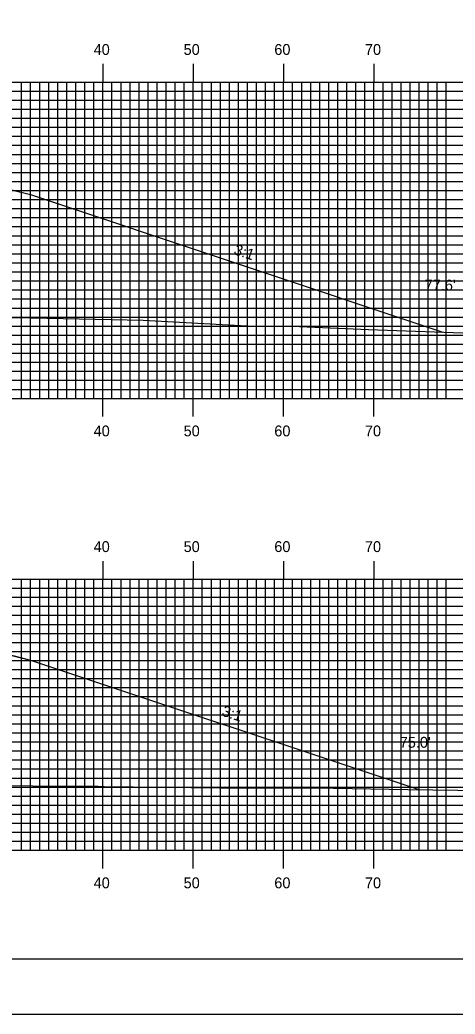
# Model space of a CAD drawing. Extents: x 1815702 to 1816046, y 442591 to 442811.
# Drawn here: x 1815898.9 to 1815947, y 442590.5 to 442700.5 of the extents above; entities that cross this region are included whole.
import ezdxf

# ---------------------------------------------------------------- set-up
doc = ezdxf.new("R2010")
doc.units = 0
for name, color, linetype in [('ANNOTATION', 7, 'Continuous'), ('BORDER', 7, 'Continuous'), ('D_Roadway_Centerline', 7, 'Continuous'), ('D_Roadway_SlopeLines', 7, 'Continuous'), ('D_Text_Standard', 7, 'Continuous'), ('H_V ANNOTATION', 7, 'Continuous'), ('MAJOR', 7, 'Continuous'), ('MINOR', 7, 'Continuous'), ('PLOT BOUNDARY', 7, 'Continuous'), ('S_Roadway_Centerline', 7, 'Continuous')]:
    doc.layers.add(name, color=color, linetype=linetype)

msp = doc.modelspace()

# ---------------------------------------------------------------- linework, layer by layer
at = {"layer": 'BORDER'}
msp.add_lwpolyline([(1815718.45, 442596.67), (1816038.45, 442596.67), (1816038.45, 442806.67), (1815718.45, 442806.67)], close=True, dxfattribs=at)
at = {"layer": 'D_Roadway_Centerline'}
for points in [[(1815809.89, 442672.49), (1815836.05, 442681.21), (1815837.87, 442681.67), (1815848.05, 442684.21), (1815856.05, 442684.53), (1815868.05, 442684.77), (1815880.05, 442684.53), (1815888.05, 442684.21), (1815898.22, 442681.67), (1815900.05, 442681.21), (1815945.68, 442666)], [(1815805.36, 442619.48), (1815836.05, 442629.71), (1815837.87, 442630.17), (1815848.05, 442632.71), (1815856.05, 442633.03), (1815868.05, 442633.27), (1815880.05, 442633.03), (1815888.05, 442632.71), (1815898.22, 442630.17), (1815900.05, 442629.71), (1815943, 442615.39)]]:
    msp.add_lwpolyline(points, dxfattribs=at)
at = {"layer": 'D_Roadway_SlopeLines'}
for points in [[(1815888.05, 442684.21), (1815900.05, 442681.21), (1815945.68, 442666)], [(1815888.05, 442632.71), (1815900.05, 442629.71), (1815943, 442615.39)]]:
    msp.add_lwpolyline(points, dxfattribs=at)
at = {"layer": 'MAJOR'}
for p, q in [((1815908.05, 442695.67), (1815908.05, 442693.67)), ((1815918.05, 442695.67), (1815918.05, 442693.67)), ((1815928.05, 442695.67), (1815928.05, 442693.67)), ((1815938.05, 442695.67), (1815938.05, 442693.67)), ((1815728.05, 442693.67), (1816008.05, 442693.67)), ((1815728.05, 442693.67), (1816008.05, 442693.67)), ((1815908.05, 442658.67), (1815908.05, 442693.67)), ((1815918.05, 442658.67), (1815918.05, 442693.67)), ((1815928.05, 442658.67), (1815928.05, 442693.67)), ((1815938.05, 442658.67), (1815938.05, 442693.67)), ((1815728.05, 442688.67), (1816008.05, 442688.67)), ((1815728.05, 442683.67), (1816008.05, 442683.67)), ((1815728.05, 442678.67), (1816008.05, 442678.67)), ((1815728.05, 442673.67), (1816008.05, 442673.67)), ((1815728.05, 442668.67), (1816008.05, 442668.67)), ((1815728.05, 442663.67), (1816008.05, 442663.67)), ((1815728.05, 442658.67), (1816008.05, 442658.67)), ((1815728.05, 442658.67), (1816008.05, 442658.67)), ((1815908.05, 442656.66), (1815908.05, 442658.67)), ((1815918.05, 442656.66), (1815918.05, 442658.67)), ((1815928.05, 442656.66), (1815928.05, 442658.67)), ((1815938.05, 442656.66), (1815938.05, 442658.67)), ((1815908.05, 442640.67), (1815908.05, 442638.67)), ((1815918.05, 442640.67), (1815918.05, 442638.67)), ((1815928.05, 442640.67), (1815928.05, 442638.67)), ((1815938.05, 442640.67), (1815938.05, 442638.67)), ((1815728.05, 442638.67), (1816008.05, 442638.67)), ((1815728.05, 442638.67), (1816008.05, 442638.67)), ((1815908.05, 442608.67), (1815908.05, 442638.67)), ((1815918.05, 442608.67), (1815918.05, 442638.67)), ((1815928.05, 442608.67), (1815928.05, 442638.67)), ((1815938.05, 442608.67), (1815938.05, 442638.67)), ((1815728.05, 442633.67), (1816008.05, 442633.67)), ((1815728.05, 442628.67), (1816008.05, 442628.67)), ((1815728.05, 442623.67), (1816008.05, 442623.67)), ((1815728.05, 442618.67), (1816008.05, 442618.67)), ((1815728.05, 442613.67), (1816008.05, 442613.67)), ((1815728.05, 442608.67), (1816008.05, 442608.67)), ((1815728.05, 442608.67), (1816008.05, 442608.67)), ((1815908.05, 442606.66), (1815908.05, 442608.67)), ((1815918.05, 442606.66), (1815918.05, 442608.67)), ((1815928.05, 442606.66), (1815928.05, 442608.67)), ((1815938.05, 442606.66), (1815938.05, 442608.67))]:
    msp.add_line(p, q, dxfattribs=at)
at = {"layer": 'MINOR'}
for p, q in [((1815899.05, 442658.67), (1815899.05, 442693.67)), ((1815900.05, 442658.67), (1815900.05, 442693.67)), ((1815901.05, 442658.67), (1815901.05, 442693.67)), ((1815902.05, 442658.67), (1815902.05, 442693.67)), ((1815903.05, 442658.67), (1815903.05, 442693.67)), ((1815904.05, 442658.67), (1815904.05, 442693.67)), ((1815905.05, 442658.67), (1815905.05, 442693.67)), ((1815906.05, 442658.67), (1815906.05, 442693.67)), ((1815907.05, 442658.67), (1815907.05, 442693.67)), ((1815909.05, 442658.67), (1815909.05, 442693.67)), ((1815910.05, 442658.67), (1815910.05, 442693.67)), ((1815911.05, 442658.67), (1815911.05, 442693.67)), ((1815912.05, 442658.67), (1815912.05, 442693.67)), ((1815913.05, 442658.67), (1815913.05, 442693.67)), ((1815914.05, 442658.67), (1815914.05, 442693.67)), ((1815915.05, 442658.67), (1815915.05, 442693.67)), ((1815916.05, 442658.67), (1815916.05, 442693.67)), ((1815917.05, 442658.67), (1815917.05, 442693.67)), ((1815919.05, 442658.67), (1815919.05, 442693.67)), ((1815920.05, 442658.67), (1815920.05, 442693.67)), ((1815921.05, 442658.67), (1815921.05, 442693.67)), ((1815922.05, 442658.67), (1815922.05, 442693.67)), ((1815923.05, 442658.67), (1815923.05, 442693.67)), ((1815924.05, 442658.67), (1815924.05, 442693.67)), ((1815925.05, 442658.67), (1815925.05, 442693.67)), ((1815926.05, 442658.67), (1815926.05, 442693.67)), ((1815927.05, 442658.67), (1815927.05, 442693.67)), ((1815929.05, 442658.67), (1815929.05, 442693.67)), ((1815930.05, 442658.67), (1815930.05, 442693.67)), ((1815931.05, 442658.67), (1815931.05, 442693.67)), ((1815932.05, 442658.67), (1815932.05, 442693.67)), ((1815933.05, 442658.67), (1815933.05, 442693.67)), ((1815934.05, 442658.67), (1815934.05, 442693.67)), ((1815935.05, 442658.67), (1815935.05, 442693.67)), ((1815936.05, 442658.67), (1815936.05, 442693.67)), ((1815937.05, 442658.67), (1815937.05, 442693.67)), ((1815939.05, 442658.67), (1815939.05, 442693.67)), ((1815940.05, 442658.67), (1815940.05, 442693.67)), ((1815941.05, 442658.67), (1815941.05, 442693.67)), ((1815942.05, 442658.67), (1815942.05, 442693.67)), ((1815943.05, 442658.67), (1815943.05, 442693.67)), ((1815944.05, 442658.67), (1815944.05, 442693.67)), ((1815945.05, 442658.67), (1815945.05, 442693.67)), ((1815946.05, 442658.67), (1815946.05, 442693.67)), ((1815728.05, 442692.67), (1816008.05, 442692.67)), ((1815728.05, 442691.67), (1816008.05, 442691.67)), ((1815728.05, 442690.67), (1816008.05, 442690.67)), ((1815728.05, 442689.67), (1816008.05, 442689.67)), ((1815728.05, 442687.67), (1816008.05, 442687.67)), ((1815728.05, 442686.67), (1816008.05, 442686.67)), ((1815728.05, 442685.67), (1816008.05, 442685.67)), ((1815728.05, 442684.67), (1816008.05, 442684.67)), ((1815728.05, 442682.67), (1816008.05, 442682.67)), ((1815728.05, 442681.67), (1816008.05, 442681.67)), ((1815728.05, 442680.67), (1816008.05, 442680.67)), ((1815728.05, 442679.67), (1816008.05, 442679.67)), ((1815728.05, 442677.67), (1816008.05, 442677.67)), ((1815728.05, 442676.67), (1816008.05, 442676.67)), ((1815728.05, 442675.67), (1816008.05, 442675.67)), ((1815728.05, 442674.67), (1816008.05, 442674.67)), ((1815728.05, 442672.67), (1816008.05, 442672.67)), ((1815728.05, 442671.67), (1816008.05, 442671.67)), ((1815728.05, 442670.67), (1816008.05, 442670.67)), ((1815728.05, 442669.67), (1816008.05, 442669.67)), ((1815728.05, 442667.67), (1816008.05, 442667.67)), ((1815728.05, 442666.67), (1816008.05, 442666.67)), ((1815728.05, 442665.67), (1816008.05, 442665.67)), ((1815728.05, 442664.67), (1816008.05, 442664.67)), ((1815728.05, 442662.67), (1816008.05, 442662.67)), ((1815728.05, 442661.67), (1816008.05, 442661.67)), ((1815728.05, 442660.67), (1816008.05, 442660.67)), ((1815728.05, 442659.67), (1816008.05, 442659.67)), ((1815899.05, 442608.67), (1815899.05, 442638.67)), ((1815900.05, 442608.67), (1815900.05, 442638.67)), ((1815901.05, 442608.67), (1815901.05, 442638.67)), ((1815902.05, 442608.67), (1815902.05, 442638.67)), ((1815903.05, 442608.67), (1815903.05, 442638.67)), ((1815904.05, 442608.67), (1815904.05, 442638.67)), ((1815905.05, 442608.67), (1815905.05, 442638.67)), ((1815906.05, 442608.67), (1815906.05, 442638.67)), ((1815907.05, 442608.67), (1815907.05, 442638.67)), ((1815909.05, 442608.67), (1815909.05, 442638.67)), ((1815910.05, 442608.67), (1815910.05, 442638.67)), ((1815911.05, 442608.67), (1815911.05, 442638.67)), ((1815912.05, 442608.67), (1815912.05, 442638.67)), ((1815913.05, 442608.67), (1815913.05, 442638.67)), ((1815914.05, 442608.67), (1815914.05, 442638.67)), ((1815915.05, 442608.67), (1815915.05, 442638.67)), ((1815916.05, 442608.67), (1815916.05, 442638.67)), ((1815917.05, 442608.67), (1815917.05, 442638.67)), ((1815919.05, 442608.67), (1815919.05, 442638.67)), ((1815920.05, 442608.67), (1815920.05, 442638.67)), ((1815921.05, 442608.67), (1815921.05, 442638.67)), ((1815922.05, 442608.67), (1815922.05, 442638.67)), ((1815923.05, 442608.67), (1815923.05, 442638.67)), ((1815924.05, 442608.67), (1815924.05, 442638.67)), ((1815925.05, 442608.67), (1815925.05, 442638.67)), ((1815926.05, 442608.67), (1815926.05, 442638.67)), ((1815927.05, 442608.67), (1815927.05, 442638.67)), ((1815929.05, 442608.67), (1815929.05, 442638.67)), ((1815930.05, 442608.67), (1815930.05, 442638.67)), ((1815931.05, 442608.67), (1815931.05, 442638.67)), ((1815932.05, 442608.67), (1815932.05, 442638.67)), ((1815933.05, 442608.67), (1815933.05, 442638.67)), ((1815934.05, 442608.67), (1815934.05, 442638.67)), ((1815935.05, 442608.67), (1815935.05, 442638.67)), ((1815936.05, 442608.67), (1815936.05, 442638.67)), ((1815937.05, 442608.67), (1815937.05, 442638.67)), ((1815939.05, 442608.67), (1815939.05, 442638.67)), ((1815940.05, 442608.67), (1815940.05, 442638.67)), ((1815941.05, 442608.67), (1815941.05, 442638.67)), ((1815942.05, 442608.67), (1815942.05, 442638.67)), ((1815943.05, 442608.67), (1815943.05, 442638.67)), ((1815944.05, 442608.67), (1815944.05, 442638.67)), ((1815945.05, 442608.67), (1815945.05, 442638.67)), ((1815946.05, 442608.67), (1815946.05, 442638.67)), ((1815728.05, 442637.67), (1816008.05, 442637.67)), ((1815728.05, 442636.67), (1816008.05, 442636.67)), ((1815728.05, 442635.67), (1816008.05, 442635.67)), ((1815728.05, 442634.67), (1816008.05, 442634.67)), ((1815728.05, 442632.67), (1816008.05, 442632.67)), ((1815728.05, 442631.67), (1816008.05, 442631.67)), ((1815728.05, 442630.67), (1816008.05, 442630.67)), ((1815728.05, 442629.67), (1816008.05, 442629.67)), ((1815728.05, 442627.67), (1816008.05, 442627.67)), ((1815728.05, 442626.67), (1816008.05, 442626.67)), ((1815728.05, 442625.67), (1816008.05, 442625.67)), ((1815728.05, 442624.67), (1816008.05, 442624.67)), ((1815728.05, 442622.67), (1816008.05, 442622.67)), ((1815728.05, 442621.67), (1816008.05, 442621.67)), ((1815728.05, 442620.67), (1816008.05, 442620.67)), ((1815728.05, 442619.67), (1816008.05, 442619.67)), ((1815728.05, 442617.67), (1816008.05, 442617.67)), ((1815728.05, 442616.67), (1816008.05, 442616.67)), ((1815728.05, 442615.67), (1816008.05, 442615.67)), ((1815728.05, 442614.67), (1816008.05, 442614.67)), ((1815728.05, 442612.67), (1816008.05, 442612.67)), ((1815728.05, 442611.67), (1816008.05, 442611.67)), ((1815728.05, 442610.67), (1816008.05, 442610.67)), ((1815728.05, 442609.67), (1816008.05, 442609.67))]:
    msp.add_line(p, q, dxfattribs=at)
at = {"layer": 'PLOT BOUNDARY'}
msp.add_lwpolyline([(1815702.26, 442590.55), (1816042.26, 442590.55), (1816042.26, 442810.55), (1815702.26, 442810.55)], close=True, dxfattribs=at)
at = {"layer": 'S_Roadway_Centerline'}
for points in [[(1815809.56, 442672.51), (1815823.05, 442671.65), (1815826.54, 442671.35), (1815836.32, 442670.69), (1815841.18, 442670.41), (1815842.31, 442670.37), (1815855.5, 442670.01), (1815860.83, 442669.64), (1815869.42, 442669.24), (1815877.56, 442668.97), (1815882.7, 442668.66), (1815894.49, 442667.72), (1815896.09, 442667.63), (1815900.12, 442667.6), (1815912.51, 442667.31), (1815923.93, 442666.7), (1815928.95, 442666.66), (1815937.45, 442666.3), (1815948.91, 442665.88), (1815962.14, 442665.79), (1815970.07, 442665.5), (1815986.57, 442665.4), (1816007.47, 442665.13), (1816008.05, 442665.13)], [(1815805.51, 442619.47), (1815817.11, 442619.1), (1815822.45, 442618.9), (1815838.94, 442618.25), (1815839.92, 442618.22), (1815840.49, 442618.19), (1815842.51, 442618.11), (1815853.16, 442617.67), (1815856.2, 442617.59), (1815861.83, 442617.35), (1815873.52, 442616.69), (1815879.92, 442616.49), (1815890.93, 442615.88), (1815904.99, 442615.76), (1815907.15, 442615.75), (1815907.54, 442615.75), (1815908.18, 442615.73), (1815924.18, 442615.54), (1815931.51, 442615.58), (1815941.78, 442615.41), (1815966.62, 442615.08)]]:
    msp.add_lwpolyline(points, dxfattribs=at)

# ---------------------------------------------------------------- texts
at = {"layer": 'ANNOTATION'}
for p in [(1815922.46, 442674.64), (1815921.13, 442623.59)]:
    msp.add_text('3:1', height=1.2, rotation=341.5652, dxfattribs=at).set_placement(p)
at = {"layer": 'D_Text_Standard'}
for s, p in [("77.6'", (1815943.67, 442670.6)), ("75.0'", (1815940.9, 442620.02))]:
    msp.add_text(s, height=1.2, dxfattribs=at).set_placement(p)
at = {"layer": 'H_V ANNOTATION'}
for s, p in [('40', (1815907.02, 442696.67)), ('50', (1815916.98, 442696.67)), ('60', (1815927.02, 442696.67)), ('70', (1815937.05, 442696.67)), ('40', (1815907.02, 442654.47)), ('50', (1815916.98, 442654.47)), ('60', (1815927.02, 442654.47)), ('70', (1815937.05, 442654.47)), ('40', (1815907.02, 442641.67)), ('50', (1815916.98, 442641.67)), ('60', (1815927.02, 442641.67)), ('70', (1815937.05, 442641.67)), ('40', (1815907.02, 442604.47)), ('50', (1815916.98, 442604.47)), ('60', (1815927.02, 442604.47)), ('70', (1815937.05, 442604.47))]:
    msp.add_text(s, height=1.2, dxfattribs=at).set_placement(p)

doc.saveas('drawing.dxf')
